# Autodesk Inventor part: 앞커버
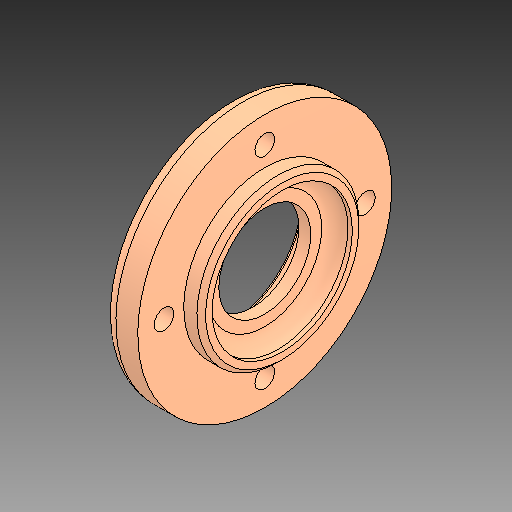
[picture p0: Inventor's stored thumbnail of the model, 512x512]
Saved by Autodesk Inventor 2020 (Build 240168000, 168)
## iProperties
Created: 2024-08
Part Number: 앞커버
Material: 알루미늄 6061
Document SubType Name: Modeling
Designer: 1강의실14
Density: 2.7 g/cm^3
Appearance: 기본값
Author: jhkim
Sending System: Autodesk Inventor 2025
Preprocessor: ST-DEVELOPER v20
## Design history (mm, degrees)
feature "솔리드1"
node "솔리드2"
